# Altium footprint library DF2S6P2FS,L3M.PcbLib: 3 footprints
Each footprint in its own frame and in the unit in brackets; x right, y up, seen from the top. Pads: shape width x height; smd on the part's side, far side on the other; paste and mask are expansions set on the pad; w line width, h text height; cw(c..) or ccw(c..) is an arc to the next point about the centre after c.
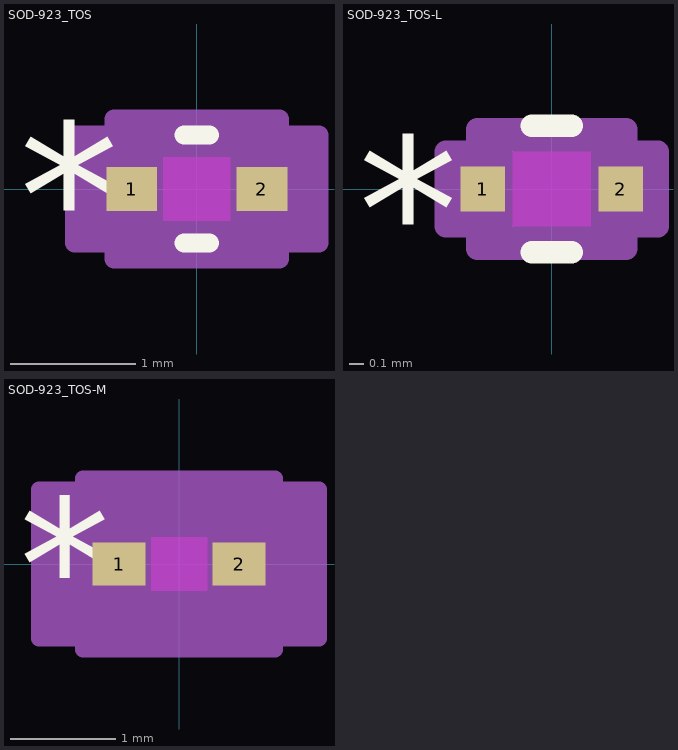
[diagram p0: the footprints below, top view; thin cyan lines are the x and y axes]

## SOD-923_TOS [mil]
pads (2):
  rect 16x14 smd paste+0 mask+0: 1(-20.5,0) 2(20.5,0)
Top Layer keep-out:
  region: -10.5,-10 -10.5,10 10.5,10 10.5,-10
Top Overlay:
  lines w6: -4.04,-17 4.04,-17 ; -4.04,17 4.04,17
  text ".Designator" at -137.5,-25 h50
  text "*" at -56,-25 h50
Keep-Out Layer:
  region: -10.5,-10 -10.5,10 10.5,10 10.5,-10
Mechanical 13:
  lines w1: -16,-6 -10,-12 ; -16,6 -10,12 ; -20.5,-7 -20.5,7 -16,7 -16,-7 -20.5,-7 ; -16,-12 16,-12 16,12 -16,12 -16,-12 ; 16,-7 16,7 20.5,7 20.5,-7 16,-7
  text "*" at -18.5,-25 h50
  text ".Designator" at -137.5,-25 h50
Mechanical 15:
  region: -26,-17 -38.5,-17 -38.5,17 -26,17 -26,22 26,22 26,17 38.5,17 38.5,-17 26,-17 26,-22 -26,-22
  lines w6: -38.5,-17 -38.5,17 -26,17 -26,22 26,22 26,17 38.5,17 38.5,-17 26,-17 26,-22 -26,-22 -26,-17 -38.5,-17
3D body "SOD-923_TOS.step": height 18.27, standoff 0, extent -20.51,-12.01 20.51,12.01

## SOD-923_TOS-L [mil]
pads (2):
  rect 12x12 smd paste+0 mask+0: 1(-18.5,0) 2(18.5,0)
Top Layer keep-out:
  region: -10.5,-10 -10.5,10 10.5,10 10.5,-10
Top Overlay:
  lines w6: -5.39,-17 5.39,-17 ; -5.39,17 5.39,17
  text ".Designator" at -137.5,-25 h50
  text "*" at -52,-25 h50
Keep-Out Layer:
  region: -10.5,-10 -10.5,10 10.5,10 10.5,-10
Mechanical 13:
  lines w1: -16,-6 -10,-12 ; -16,6 -10,12 ; -20.5,-7 -20.5,7 -16,7 -16,-7 -20.5,-7 ; -16,-12 16,-12 16,12 -16,12 -16,-12 ; 16,-7 16,7 20.5,7 20.5,-7 16,-7
  text "*" at -18.5,-25 h50
  text ".Designator" at -137.5,-25 h50
Mechanical 15:
  region: -20,-10 -28.5,-10 -28.5,10 -20,10 -20,16 20,16 20,10 28.5,10 28.5,-10 20,-10 20,-16 -20,-16
  lines w6: -28.5,-10 -28.5,10 -20,10 -20,16 20,16 20,10 28.5,10 28.5,-10 20,-10 20,-16 -20,-16 -20,-10 -28.5,-10
3D body "SOD-923_TOS.step": height 18.27, standoff 0, extent -20.51,-12.01 20.51,12.01

## SOD-923_TOS-M [mil]
pads (2):
  rect 20x16 smd paste+0 mask+0: 1(-22.5,0) 2(22.5,0)
Top Layer keep-out:
  region: -10.5,-10 -10.5,10 10.5,10 10.5,-10
Top Overlay:
  text ".Designator" at -137.5,-25 h50
  text "*" at -60,-25 h50
Keep-Out Layer:
  region: -10.5,-10 -10.5,10 10.5,10 10.5,-10
Mechanical 13:
  lines w1: -16,-6 -10,-12 ; -16,6 -10,12 ; -20.5,-7 -20.5,7 -16,7 -16,-7 -20.5,-7 ; -16,-12 16,-12 16,12 -16,12 -16,-12 ; 16,-7 16,7 20.5,7 20.5,-7 16,-7
  text "*" at -18.5,-25 h50
  text ".Designator" at -137.5,-25 h50
Mechanical 15:
  region: -36,-28 -52.5,-28 -52.5,28 -36,28 -36,32 36,32 36,28 52.5,28 52.5,-28 36,-28 36,-32 -36,-32
  lines w6: -52.5,-28 -52.5,28 -36,28 -36,32 36,32 36,28 52.5,28 52.5,-28 36,-28 36,-32 -36,-32 -36,-28 -52.5,-28
3D body "SOD-923_TOS.step": height 18.27, standoff 0, extent -20.51,-12.01 20.51,12.01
